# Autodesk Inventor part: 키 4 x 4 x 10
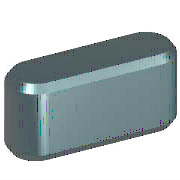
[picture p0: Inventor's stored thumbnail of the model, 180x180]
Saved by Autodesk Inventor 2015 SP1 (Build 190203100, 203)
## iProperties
IsCustomPart: 1
Created: 2012-02
Part Number: 키 4 x 4 x 10
Material: 강철, 연강
Description: 키 및 해당 키홈
Document SubType Name: Modeling
Standard: KS B 1311
Designer: test
Standards Organization: KS
Language: ko-KR
Size Designation: 4 x 4 x 10
Categories: <MemberInstance><Categories><Category DisplayName="샤프트 부품" InternalName="7f7aeb1f-a693-4053-b835-cee3144e0d98" Mnemonic="SHFT"><Category DisplayName="키" Interna
Density: 1 g/cm^3
Appearance: 노란색
Author: test
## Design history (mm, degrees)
workplane "Work Plane1"
workplane "Work Plane2"
sketch "스케치1"
  geometry: L1 (2, 2)-(8, 2); L2 (8, -2)-(2, -2); L3 (0, 9.4)-(0, -7.4) reference; L4 (-5, 0)-(30, 0) reference; L5 (10, 0)-(10, 7); A1 r 2 centre (2, 0) between (2, 2) and (2, -2); A2 r 2 centre (8, 0) between (8, -2) and (8, 2)
  constraints: 6 end point, 5 point on circle, 4 tangent, 3 point on line, 2 centre point, 1 horizontal, 1 parallel, 1 perpendicular
  dimensions: "d0" = 2 radius of A1 (= 0.5 x PB); "d13" = 2 radius of A2 (= 0.5 x PB); "d14" = 10 distance between parallel lines of L5 L3 (= NLG)
extrude "본체1" new body sketch "스케치1" taper "d3" = 0 deg; stored distance "d4" = 10
workplane "Work Plane3"
body "Solid1"
chamfer "모따기1" distance "d8" = 0.25 (= PHH); stored, may be unused: second distance "d9" = 0.25 (= PHH), angle "d15" = 45 deg
other parameters: "d1" = -2.5 (= -PNT), "d2" = 1.5 (= PH - PNT), "NLG" = 10 [user parameter; used in 3 equation terms], "PB" = 4 [user parameter; used in 2 equation terms], "PNT" = 2.5 [user parameter; used in 2 equation terms], "PH" = 4 [user parameter; used in 1 equation term], "PHH" = 0.25 [user parameter; used in 2 equation terms], "d10" = 0, "d16" = 0, "d17" = 0, "d18" = 0, "WDMAX" = 12 [user parameter], "RR" = 0.08 [user parameter], "PUEB" = 1.8 [user parameter]
